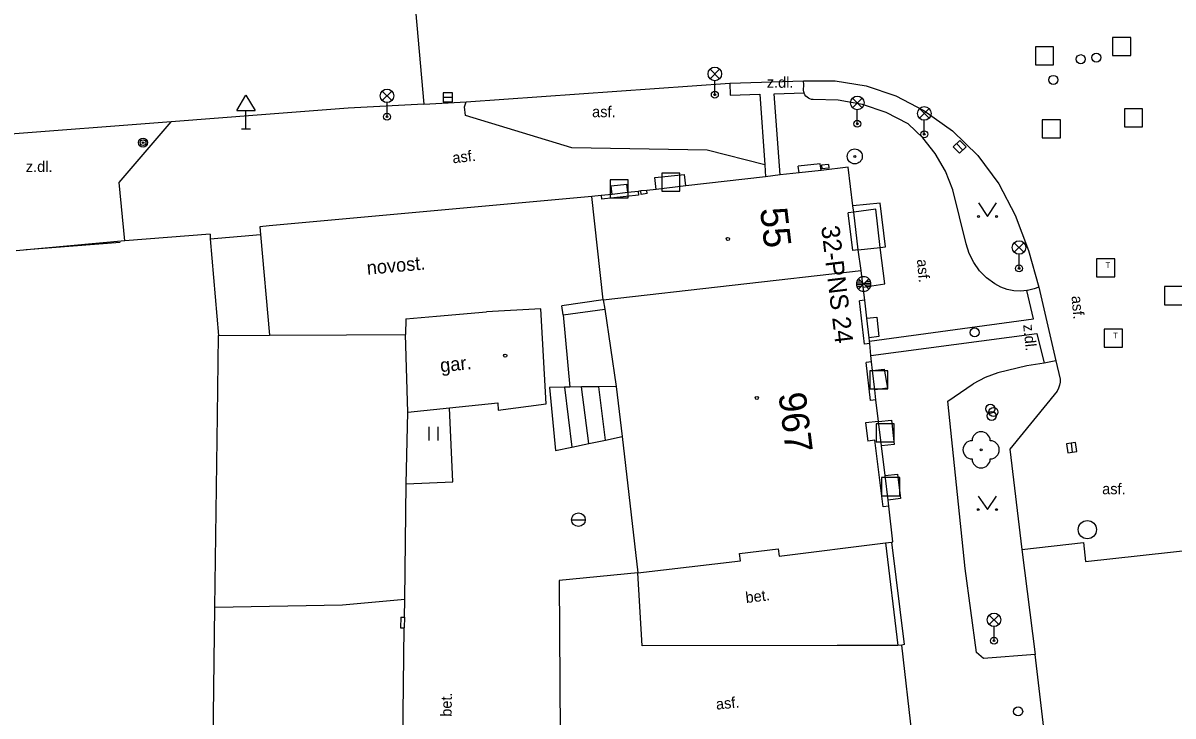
# Model space of a CAD drawing. Extents: x -642282 to -641982, y -1041678 to -1041427.
# Drawn here: x -642233.5 to -642170.1, y -1041615 to -1041576.8 of the extents above; entities that cross this region are included whole.
import ezdxf

# ---------------------------------------------------------------- set-up
doc = ezdxf.new("R2010")
doc.units = 0
for name, color, linetype in [('Budovy', 7, 'Continuous'), ('Budovy vstupy', 7, 'Continuous'), ('Nivel_zn_-popis', 7, 'Continuous'), ('Nivel_značky', 7, 'Continuous'), ('Ploty', 7, 'Continuous'), ('Pol_bod_pole', 7, 'Continuous'), ('Popis objektů', 7, 'Continuous'), ('Popis povrchů', 7, 'Continuous'), ('Popis ČP_ ČE', 7, 'Continuous'), ('Pris-HUP', 7, 'Continuous'), ('Rozhraní ploch 1', 7, 'Continuous'), ('Rozhraní ploch 2', 7, 'Continuous'), ('Sloupy_označník', 7, 'Continuous'), ('Vstup na pozemky', 7, 'Continuous'), ('Zeleň - stromy', 7, 'Continuous'), ('Znaky doprava', 7, 'Continuous'), ('Znaky kanalizace', 7, 'Continuous'), ('Znaky voda', 7, 'Continuous'), ('Značky doprava', 7, 'Continuous'), ('Značky KM', 7, 'Continuous'), ('Značky předmětů', 7, 'Continuous'), ('Značky těžba', 7, 'Continuous'), ('Šachta teplo', 7, 'Continuous'), ('Šachty ner_', 7, 'Continuous')]:
    doc.layers.add(name, color=color, linetype=linetype)

msp = doc.modelspace()

# ---------------------------------------------------------------- linework, layer by layer
at = {"layer": 'Budovy'}
for p, q in [((-642188.02, -1041584.72), (-642189.518, -1041584.892)), ((-642187.762, -1041586.844), (-642188.02, -1041584.72)), ((-642192.575, -1041585.236), (-642196.959, -1041585.747)), ((-642191.765, -1041585.143), (-642192.575, -1041585.236)), ((-642190.726, -1041585.031), (-642191.765, -1041585.143)), ((-642189.518, -1041584.892), (-642190.726, -1041585.031)), ((-642198.594, -1041585.934), (-642199.116, -1041585.994)), ((-642196.959, -1041585.747), (-642198.594, -1041585.934)), ((-642202.14, -1041586.33), (-642219.914, -1041587.952)), ((-642201.64, -1041586.28), (-642202.14, -1041586.33)), ((-642201.515, -1041592.02), (-642202.14, -1041586.33)), ((-642201.027, -1041586.211), (-642201.64, -1041586.28)), ((-642201.64, -1041586.28), (-642201.618, -1041586.479)), ((-642199.578, -1041586.249), (-642201.618, -1041586.479)), ((-642200.161, -1041586.113), (-642201.027, -1041586.211)), ((-642199.6, -1041586.05), (-642200.161, -1041586.113)), ((-642199.45, -1041586.02), (-642199.6, -1041586.05)), ((-642199.6, -1041586.05), (-642199.578, -1041586.249)), ((-642199.116, -1041585.994), (-642199.45, -1041586.02)), ((-642187.72, -1041587.19), (-642188.018, -1041587.226)), ((-642187.768, -1041589.306), (-642188.018, -1041587.226)), ((-642187.72, -1041587.19), (-642187.762, -1041586.844)), ((-642187.47, -1041589.27), (-642187.72, -1041587.19)), ((-642223.171, -1041588.406), (-642227.872, -1041588.766)), ((-642219.914, -1041587.952), (-642220.44, -1041588)), ((-642220.44, -1041588), (-642220.401, -1041588.424)), ((-642220.401, -1041588.424), (-642219.895, -1041593.974)), ((-642227.872, -1041588.766), (-642233.854, -1041589.321)), ((-642223.167, -1041588.668), (-642222.72, -1041593.99)), ((-642187.47, -1041589.27), (-642187.768, -1041589.306)), ((-642187.308, -1041590.4), (-642187.47, -1041589.27)), ((-642201.515, -1041592.02), (-642187.308, -1041590.4)), ((-642187.197, -1041591.322), (-642187.308, -1041590.4)), ((-642187.11, -1041592.04), (-642187.197, -1041591.322)), ((-642201.515, -1041592.02), (-642201.438, -1041592.538)), ((-642187.11, -1041592.04), (-642187.408, -1041592.075)), ((-642187.128, -1041594.465), (-642187.408, -1041592.075)), ((-642186.993, -1041593.035), (-642187.11, -1041592.04)), ((-642212.4, -1041593.07), (-642210.71, -1041592.93)), ((-642210.71, -1041592.93), (-642207.953, -1041592.68)), ((-642204.958, -1041592.512), (-642207.953, -1041592.68)), ((-642204.665, -1041597.747), (-642204.958, -1041592.512)), ((-642201.438, -1041592.538), (-642200.805, -1041596.8)), ((-642212.4, -1041593.07), (-642212.41, -1041593.93)), ((-642186.868, -1041594.109), (-642186.993, -1041593.035)), ((-642222.77, -1041598.39), (-642222.72, -1041593.99)), ((-642222.72, -1041593.99), (-642219.895, -1041593.974)), ((-642219.895, -1041593.974), (-642215.66, -1041593.95)), ((-642215.66, -1041593.95), (-642212.41, -1041593.93)), ((-642212.275, -1041598.207), (-642212.41, -1041593.93)), ((-642186.845, -1041594.303), (-642186.868, -1041594.109)), ((-642186.83, -1041594.43), (-642187.128, -1041594.465)), ((-642186.83, -1041594.43), (-642186.845, -1041594.303)), ((-642186.771, -1041595.088), (-642186.83, -1041594.43)), ((-642186.74, -1041595.44), (-642187.038, -1041595.474)), ((-642186.796, -1041597.571), (-642187.038, -1041595.474)), ((-642186.74, -1041595.44), (-642186.771, -1041595.088)), ((-642186.685, -1041595.915), (-642186.74, -1041595.44)), ((-642186.563, -1041596.975), (-642186.685, -1041595.915)), ((-642200.805, -1041596.8), (-642200.483, -1041599.557)), ((-642186.498, -1041597.537), (-642186.563, -1041596.975)), ((-642212.275, -1041598.207), (-642209.98, -1041597.972)), ((-642209.98, -1041597.972), (-642207.322, -1041597.699)), ((-642207.322, -1041597.699), (-642207.313, -1041598.099)), ((-642207.313, -1041598.099), (-642204.665, -1041597.747)), ((-642186.498, -1041597.537), (-642186.796, -1041597.571)), ((-642186.36, -1041598.73), (-642186.498, -1041597.537)), ((-642222.91, -1041608.98), (-642222.77, -1041598.39)), ((-642212.379, -1041602.169), (-642212.275, -1041598.207)), ((-642186.36, -1041598.73), (-642187.063, -1041598.811)), ((-642187.063, -1041598.811), (-642186.947, -1041599.809)), ((-642186.193, -1041600.076), (-642186.36, -1041598.73)), ((-642200.483, -1041599.557), (-642199.604, -1041607.074)), ((-642186.55, -1041599.76), (-642186.947, -1041599.809)), ((-642186.094, -1041603.433), (-642186.55, -1041599.76)), ((-642185.991, -1041601.704), (-642186.193, -1041600.076)), ((-642185.822, -1041603.058), (-642185.991, -1041601.704)), ((-642212.452, -1041608.543), (-642212.379, -1041602.169)), ((-642185.78, -1041603.4), (-642185.822, -1041603.058)), ((-642185.78, -1041603.4), (-642186.094, -1041603.433)), ((-642185.562, -1041605.368), (-642185.78, -1041603.4)), ((-642191.831, -1041606.151), (-642185.97, -1041605.416)), ((-642185.97, -1041605.416), (-642185.632, -1041605.386)), ((-642185.632, -1041605.386), (-642185.562, -1041605.368)), ((-642194.006, -1041606.007), (-642191.878, -1041605.754)), ((-642193.959, -1041606.404), (-642194.006, -1041606.007)), ((-642191.878, -1041605.754), (-642191.831, -1041606.151)), ((-642199.604, -1041607.074), (-642193.959, -1041606.404)), ((-642212.452, -1041608.543), (-642215.88, -1041608.86)), ((-642212.47, -1041609.52), (-642212.452, -1041608.543)), ((-642223.08, -1041622.83), (-642222.91, -1041608.98)), ((-642215.88, -1041608.86), (-642222.91, -1041608.98)), ((-642212.47, -1041609.52), (-642212.48, -1041610.1)), ((-642212.692, -1041625.83), (-642212.48, -1041610.1))]:
    msp.add_line(p, q, dxfattribs=at)
msp.add_lwpolyline([(-642223.171, -1041588.406), (-642223.167, -1041588.668)], dxfattribs=at)
at = {"layer": 'Budovy vstupy'}
msp.add_line((-642228.136, -1041588.865), (-642233.302, -1041589.262), dxfattribs=at)
at = {"layer": 'Nivel_značky'}
for p, q in [((-642187.328, -1041590.999), (-642187.519, -1041590.999)), ((-642187.17, -1041591.15), (-642187.455, -1041590.865)), ((-642186.885, -1041590.865), (-642187.17, -1041591.15)), ((-642186.822, -1041591.015), (-642187.025, -1041591.015)), ((-642187.244, -1041591.11), (-642187.57, -1041591.11)), ((-642187.244, -1041591.205), (-642187.542, -1041591.205)), ((-642187.345, -1041591.31), (-642187.531, -1041591.31)), ((-642187.455, -1041591.435), (-642187.17, -1041591.15)), ((-642187.17, -1041591.15), (-642186.885, -1041591.435)), ((-642186.794, -1041591.115), (-642187.115, -1041591.115)), ((-642186.8, -1041591.215), (-642187.081, -1041591.215)), ((-642186.828, -1041591.305), (-642187.008, -1041591.305))]:
    msp.add_line(p, q, dxfattribs=at)
for start, end in [(135, 225), (45, 135), (315, 45), (225, 315)]:
    msp.add_arc((-642187.17, -1041591.15), 0.403, start, end, dxfattribs=at)
at = {"layer": 'Ploty'}
for p, q in [((-642223.167, -1041588.668), (-642220.401, -1041588.424)), ((-642201.515, -1041592.02), (-642203.804, -1041592.363)), ((-642203.73, -1041592.857), (-642203.804, -1041592.363)), ((-642203.73, -1041592.857), (-642201.438, -1041592.538)), ((-642185.97, -1041605.416), (-642185.295, -1041611.069)), ((-642185.632, -1041605.386), (-642184.948, -1041611.027)), ((-642185.061, -1041611.058), (-642185.295, -1041611.069)), ((-642184.948, -1041611.027), (-642185.061, -1041611.058))]:
    msp.add_line(p, q, dxfattribs=at)
at = {"layer": 'Pol_bod_pole'}
for radius in [0.412, 0.05]:
    msp.add_circle((-642187.66, -1041584.12), radius, dxfattribs=at)
at = {"layer": 'Pris-HUP'}
for p, q in [((-642189.56, -1041584.53), (-642190.77, -1041584.65)), ((-642190.726, -1041585.031), (-642190.77, -1041584.65)), ((-642189.518, -1041584.892), (-642189.56, -1041584.53)), ((-642189.11, -1041584.56), (-642189.49, -1041584.6)), ((-642189.49, -1041584.6), (-642189.469, -1041584.799)), ((-642189.11, -1041584.56), (-642189.089, -1041584.759)), ((-642189.089, -1041584.759), (-642189.469, -1041584.799)), ((-642199.42, -1041586.218), (-642199.45, -1041586.02)), ((-642199.09, -1041586.168), (-642199.42, -1041586.218)), ((-642199.09, -1041586.168), (-642199.116, -1041585.994)), ((-642212.67, -1041609.517), (-642212.68, -1041610.097)), ((-642212.67, -1041609.517), (-642212.47, -1041609.52)), ((-642212.68, -1041610.097), (-642212.48, -1041610.1))]:
    msp.add_line(p, q, dxfattribs=at)
at = {"layer": 'Rozhraní ploch 1'}
for p, q in [((-642211.41, -1041581.24), (-642215.565, -1041581.462)), ((-642225.323, -1041582.22), (-642236.723, -1041583.094)), ((-642203.73, -1041592.857), (-642203.361, -1041596.833)), ((-642186.993, -1041593.035), (-642186.439, -1041592.97)), ((-642186.439, -1041592.97), (-642186.334, -1041594.047)), ((-642186.334, -1041594.047), (-642186.868, -1041594.109)), ((-642186.685, -1041595.915), (-642186.036, -1041595.84)), ((-642186.036, -1041595.84), (-642185.861, -1041596.893)), ((-642182.53, -1041597.61), (-642181.14, -1041596.66)), ((-642203.66, -1041596.837), (-642204.469, -1041596.847)), ((-642204.469, -1041596.847), (-642204.148, -1041600.333)), ((-642203.361, -1041596.833), (-642203.66, -1041596.837)), ((-642203.66, -1041596.837), (-642203.243, -1041600.141)), ((-642202.712, -1041596.824), (-642203.361, -1041596.833)), ((-642201.768, -1041596.812), (-642202.712, -1041596.824)), ((-642202.319, -1041599.946), (-642202.712, -1041596.824)), ((-642200.805, -1041596.8), (-642201.768, -1041596.812)), ((-642201.397, -1041599.751), (-642201.768, -1041596.812)), ((-642185.861, -1041596.893), (-642186.563, -1041596.975)), ((-642209.797, -1041602.061), (-642209.98, -1041597.972)), ((-642181.57, -1041606.84), (-642182.53, -1041597.61)), ((-642186.36, -1041598.73), (-642185.629, -1041598.655)), ((-642185.629, -1041598.655), (-642185.485, -1041599.993)), ((-642202.319, -1041599.946), (-642201.397, -1041599.751)), ((-642201.397, -1041599.751), (-642200.483, -1041599.557)), ((-642204.148, -1041600.333), (-642203.243, -1041600.141)), ((-642203.243, -1041600.141), (-642202.319, -1041599.946)), ((-642185.485, -1041599.993), (-642186.193, -1041600.076)), ((-642185.991, -1041601.704), (-642185.306, -1041601.624)), ((-642185.306, -1041601.624), (-642185.142, -1041602.979)), ((-642212.379, -1041602.169), (-642209.797, -1041602.061)), ((-642185.142, -1041602.979), (-642185.822, -1041603.058)), ((-642178.45, -1041605.79), (-642177.73, -1041611.57)), ((-642180.96, -1041611.46), (-642181.57, -1041606.84)), ((-642199.604, -1041607.074), (-642203.947, -1041607.486)), ((-642203.947, -1041607.486), (-642203.888, -1041615.923)), ((-642199.367, -1041611.101), (-642199.604, -1041607.074)), ((-642188.631, -1041611.067), (-642199.367, -1041611.101)), ((-642185.295, -1041611.069), (-642188.631, -1041611.067)), ((-642180.56, -1041611.8), (-642180.96, -1041611.46)), ((-642177.73, -1041611.57), (-642180.56, -1041611.8)), ((-642177.25, -1041615.63), (-642177.73, -1041611.57))]:
    msp.add_line(p, q, dxfattribs=at)
for points in [[(-642209.07, -1041581.11), (-642194.55, -1041580.09)], [(-642194.55, -1041580.09), (-642190.48, -1041579.95), (-642188.748, -1041579.955), (-642187.039, -1041580.234), (-642185.396, -1041580.78)], [(-642190.47, -1041580.18), (-642190.48, -1041579.95)], [(-642182.669, -1041584.927), (-642183.223, -1041583.964), (-642183.912, -1041583.092), (-642184.72, -1041582.33), (-642185.938, -1041581.704), (-642187.234, -1041581.265), (-642188.582, -1041581.022), (-642189.95, -1041580.98), (-642190.041, -1041580.973), (-642190.13, -1041580.95), (-642190.213, -1041580.912), (-642190.288, -1041580.86), (-642190.35, -1041580.8), (-642190.407, -1041580.722), (-642190.446, -1041580.639), (-642190.455, -1041580.613), (-642190.471, -1041580.551), (-642190.48, -1041580.46), (-642190.47, -1041580.18)], [(-642185.396, -1041580.78), (-642183.86, -1041581.58), (-642182.276, -1041582.711), (-642180.887, -1041584.075), (-642179.725, -1041585.637), (-642178.82, -1041587.36)], [(-642215.565, -1041581.462), (-642220.347, -1041581.834), (-642225.323, -1041582.22)], [(-642211.41, -1041581.24), (-642209.07, -1041581.11)], [(-642177.52, -1041591.32), (-642177.77, -1041591.41), (-642178.136, -1041591.504), (-642178.173, -1041591.508), (-642178.512, -1041591.543), (-642178.889, -1041591.526), (-642179.26, -1041591.454), (-642179.616, -1041591.328), (-642179.95, -1041591.15), (-642180.396, -1041590.817), (-642180.786, -1041590.42), (-642181.11, -1041589.967), (-642181.36, -1041589.47), (-642181.53, -1041588.94), (-642182.26, -1041585.96), (-642182.669, -1041584.927)], [(-642178.82, -1041587.36), (-642178.082, -1041589.311)], [(-642178.082, -1041589.311), (-642177.52, -1041591.32), (-642176.583, -1041595.381), (-642176.35, -1041596.39), (-642176.354, -1041596.562), (-642176.38, -1041596.72), (-642176.435, -1041596.895), (-642176.51, -1041597.05)], [(-642176.583, -1041595.381), (-642177.22, -1041595.51), (-642178.187, -1041595.666), (-642179.77, -1041596.05)], [(-642179.77, -1041596.05), (-642180.477, -1041596.305), (-642181.14, -1041596.66)], [(-642176.51, -1041597.05), (-642179.12, -1041600.26)], [(-642179.12, -1041600.26), (-642178.45, -1041605.79)]]:
    msp.add_lwpolyline(points, dxfattribs=at)
at = {"layer": 'Rozhraní ploch 2'}
for p, q in [((-642203.24, -1041583.64), (-642209.11, -1041581.87)), ((-642195.79, -1041583.78), (-642203.24, -1041583.64)), ((-642192.62, -1041584.586), (-642195.79, -1041583.78)), ((-642198.67, -1041585.284), (-642197.032, -1041585.117)), ((-642198.594, -1041585.934), (-642198.67, -1041585.284)), ((-642196.959, -1041585.747), (-642197.032, -1041585.117)), ((-642201.082, -1041585.732), (-642200.215, -1041585.649)), ((-642201.027, -1041586.211), (-642201.082, -1041585.732)), ((-642200.161, -1041586.113), (-642200.215, -1041585.649)), ((-642186.27, -1041586.69), (-642187.762, -1041586.844)), ((-642186.5, -1041587.02), (-642187.72, -1041587.19)), ((-642186.27, -1041589.14), (-642186.5, -1041587.02)), ((-642185.96, -1041589.11), (-642186.27, -1041586.69)), ((-642187.47, -1041589.27), (-642186.27, -1041589.14)), ((-642186.27, -1041589.14), (-642185.96, -1041589.11)), ((-642186.01, -1041591.14), (-642186.27, -1041589.14)), ((-642187.197, -1041591.322), (-642186.01, -1041591.14)), ((-642177.82, -1041593.07), (-642178.173, -1041591.508)), ((-642186.845, -1041594.303), (-642177.82, -1041593.07)), ((-642186.771, -1041595.088), (-642177.63, -1041593.87)), ((-642177.63, -1041593.87), (-642177.22, -1041595.51))]:
    msp.add_line(p, q, dxfattribs=at)
for points in [[(-642212.04, -1041573.97), (-642211.41, -1041581.24)], [(-642194.55, -1041580.09), (-642194.516, -1041580.736), (-642192.89, -1041580.68), (-642192.62, -1041584.586), (-642192.575, -1041585.236)], [(-642191.765, -1041585.143), (-642192.1, -1041580.67), (-642190.455, -1041580.613)], [(-642209.11, -1041581.87), (-642209.16, -1041581.38), (-642209.07, -1041581.11)], [(-642227.872, -1041588.766), (-642228.188, -1041585.548), (-642225.323, -1041582.22)], [(-642178.45, -1041605.79), (-642175.06, -1041605.39), (-642174.95, -1041606.44)], [(-642174.95, -1041606.44), (-642168.77, -1041605.77)]]:
    msp.add_lwpolyline(points, dxfattribs=at)
at = {"layer": 'Sloupy_označník'}
for radius in [0.25, 0.158, 0.05]:
    msp.add_circle((-642226.87, -1041583.36), radius, dxfattribs=at)
at = {"layer": 'Vstup na pozemky'}
msp.add_line((-642184.49, -1041616.05), (-642185.061, -1041611.058), dxfattribs=at)
at = {"layer": 'Zeleň - stromy'}
msp.add_circle((-642180.7, -1041600.29), 0.05, dxfattribs=at)
for centre, start, end in [((-642180.7, -1041599.79), 0, 180), ((-642181.2, -1041600.29), 90, 270), ((-642180.2, -1041600.29), 270, 90), ((-642180.7, -1041600.79), 180, 0)]:
    msp.add_arc(centre, 0.5, start, end, dxfattribs=at)
at = {"layer": 'Znaky doprava'}
for p, q in [((-642195.635, -1041579.305), (-642195.105, -1041579.835)), ((-642195.635, -1041579.835), (-642195.105, -1041579.305)), ((-642195.37, -1041580.72), (-642195.37, -1041579.945)), ((-642213.695, -1041580.515), (-642213.165, -1041581.045)), ((-642213.695, -1041581.045), (-642213.165, -1041580.515)), ((-642187.785, -1041580.905), (-642187.255, -1041581.435)), ((-642187.785, -1041581.435), (-642187.255, -1041580.905)), ((-642213.43, -1041581.93), (-642213.43, -1041581.155)), ((-642187.52, -1041582.32), (-642187.52, -1041581.545)), ((-642184.095, -1041581.485), (-642183.565, -1041582.015)), ((-642184.095, -1041582.015), (-642183.565, -1041581.485)), ((-642183.83, -1041582.9), (-642183.83, -1041582.125)), ((-642178.875, -1041588.875), (-642178.345, -1041589.405)), ((-642178.875, -1041589.405), (-642178.345, -1041588.875)), ((-642178.61, -1041590.29), (-642178.61, -1041589.515)), ((-642180.255, -1041609.395), (-642179.725, -1041609.925)), ((-642180.255, -1041609.925), (-642179.725, -1041609.395)), ((-642179.99, -1041610.81), (-642179.99, -1041610.035))]:
    msp.add_line(p, q, dxfattribs=at)
for centre, radius in [((-642195.37, -1041579.57), 0.375), ((-642213.43, -1041580.78), 0.375), ((-642195.37, -1041580.72), 0.19), ((-642195.37, -1041580.72), 0.05), ((-642187.52, -1041581.17), 0.375), ((-642183.83, -1041581.75), 0.375), ((-642213.43, -1041581.93), 0.19), ((-642213.43, -1041581.93), 0.05), ((-642187.52, -1041582.32), 0.19), ((-642187.52, -1041582.32), 0.05), ((-642183.83, -1041582.9), 0.19), ((-642183.83, -1041582.9), 0.05), ((-642178.61, -1041589.14), 0.375), ((-642178.61, -1041590.29), 0.19), ((-642178.61, -1041590.29), 0.05), ((-642179.99, -1041609.66), 0.375), ((-642179.99, -1041610.81), 0.19), ((-642179.99, -1041610.81), 0.05)]:
    msp.add_circle(centre, radius, dxfattribs=at)
at = {"layer": 'Znaky kanalizace'}
for p, q in [((-642210.33, -1041580.86), (-642209.83, -1041580.86)), ((-642182.056, -1041583.412), (-642181.704, -1041583.768)), ((-642175.741, -1041599.922), (-642175.679, -1041600.418))]:
    msp.add_line(p, q, dxfattribs=at)
for points in [[(-642210.33, -1041581.11), (-642209.83, -1041581.11), (-642209.83, -1041580.61), (-642210.33, -1041580.61)], [(-642182.234, -1041583.588), (-642181.882, -1041583.944), (-642181.526, -1041583.592), (-642181.878, -1041583.236)], [(-642175.989, -1041599.953), (-642175.927, -1041600.449), (-642175.431, -1041600.387), (-642175.493, -1041599.891)]]:
    msp.add_lwpolyline(points, close=True, dxfattribs=at)
msp.add_circle((-642174.85, -1041604.69), 0.5, dxfattribs=at)
at = {"layer": 'Znaky voda'}
for centre in [(-642175.21, -1041578.76), (-642174.35, -1041578.67), (-642176.72, -1041579.9), (-642181.06, -1041593.82), (-642180.19, -1041598.03), (-642180.02, -1041598.21), (-642180.12, -1041598.42), (-642178.66, -1041614.71)]:
    msp.add_circle(centre, 0.25, dxfattribs=at)
at = {"layer": 'Značky doprava'}
for p, q in [((-642221.7, -1041581.59), (-642221.2, -1041580.74)), ((-642221.2, -1041580.74), (-642220.7, -1041581.59)), ((-642221.7, -1041581.59), (-642220.7, -1041581.59)), ((-642221.2, -1041582.59), (-642221.2, -1041581.59)), ((-642221.45, -1041582.59), (-642220.95, -1041582.59))]:
    msp.add_line(p, q, dxfattribs=at)
at = {"layer": 'Značky KM'}
for p, q in [((-642180.847, -1041586.682), (-642180.347, -1041587.432)), ((-642180.347, -1041587.432), (-642179.847, -1041586.682)), ((-642211.103, -1041599.772), (-642211.103, -1041599.022)), ((-642210.603, -1041599.772), (-642210.603, -1041599.022)), ((-642180.856, -1041602.835), (-642180.356, -1041603.585)), ((-642180.356, -1041603.585), (-642179.856, -1041602.835))]:
    msp.add_line(p, q, dxfattribs=at)
for centre in [(-642180.847, -1041587.432), (-642179.847, -1041587.432), (-642180.856, -1041603.585), (-642179.856, -1041603.585)]:
    msp.add_circle(centre, 0.05, dxfattribs=at)
at = {"layer": 'Značky předmětů'}
for centre in [(-642194.651, -1041588.667), (-642206.917, -1041595.1), (-642193.054, -1041597.432)]:
    msp.add_circle(centre, 0.0875, dxfattribs=at)
at = {"layer": 'Značky těžba'}
msp.add_line((-642203.259, -1041604.142), (-642202.509, -1041604.142), dxfattribs=at)
msp.add_circle((-642202.884, -1041604.142), 0.375, dxfattribs=at)
at = {"layer": 'Šachta teplo'}
for points in [[(-642174.34, -1041590.76), (-642173.34, -1041590.76), (-642173.34, -1041589.76), (-642174.34, -1041589.76)], [(-642170.59, -1041592.29), (-642169.59, -1041592.29), (-642169.59, -1041591.29), (-642170.59, -1041591.29)], [(-642173.92, -1041594.64), (-642172.92, -1041594.64), (-642172.92, -1041593.64), (-642173.92, -1041593.64)]]:
    msp.add_lwpolyline(points, close=True, dxfattribs=at)
at = {"layer": 'Šachty ner_'}
for points in [[(-642173.46, -1041578.56), (-642172.46, -1041578.56), (-642172.46, -1041577.56), (-642173.46, -1041577.56)], [(-642177.71, -1041579.07), (-642176.71, -1041579.07), (-642176.71, -1041578.07), (-642177.71, -1041578.07)], [(-642172.81, -1041582.49), (-642171.81, -1041582.49), (-642171.81, -1041581.49), (-642172.81, -1041581.49)], [(-642177.33, -1041583.1), (-642176.33, -1041583.1), (-642176.33, -1041582.1), (-642177.33, -1041582.1)], [(-642198.29, -1041586.04), (-642197.29, -1041586.04), (-642197.29, -1041585.04), (-642198.29, -1041585.04)], [(-642201.14, -1041586.41), (-642200.14, -1041586.41), (-642200.14, -1041585.41), (-642201.14, -1041585.41)], [(-642186.83, -1041596.93), (-642185.83, -1041596.93), (-642185.83, -1041595.93), (-642186.83, -1041595.93)], [(-642186.49, -1041599.85), (-642185.49, -1041599.85), (-642185.49, -1041598.85), (-642186.49, -1041598.85)], [(-642186.18, -1041602.82), (-642185.18, -1041602.82), (-642185.18, -1041601.82), (-642186.18, -1041601.82)]]:
    msp.add_lwpolyline(points, close=True, dxfattribs=at)

# ---------------------------------------------------------------- texts
at = {"layer": 'Nivel_zn_-popis'}
msp.add_text('32-PNS 24', height=1, rotation=276.86482, dxfattribs=at).set_placement((-642189.513, -1041587.983))
at = {"layer": 'Popis objektů'}
for s, rotation, p in [('novost.', 5.21419, (-642214.513, -1041590.641)), ('gar.', 5.86422, (-642210.466, -1041596.013))]:
    msp.add_text(s, height=0.75, rotation=rotation, dxfattribs=at).set_placement(p)
at = {"layer": 'Popis povrchů'}
for s, p in [('z.dl.', (-642192.508, -1041580.338)), ('asf.', (-642202.132, -1041581.956)), ('z.dl.', (-642233.328, -1041584.977)), ('asf.', (-642174.032, -1041602.74))]:
    msp.add_text(s, height=0.6, dxfattribs=at).set_placement(p)
for s, rotation, p in [('asf.', 6.54773, (-642209.798, -1041584.502)), ('asf.', 275.08638, (-642184.237, -1041589.804)), ('asf.', 275.08638, (-642175.722, -1041591.825)), ('z.dl.', 275.96056, (-642178.385, -1041593.401)), ('bet.', 6.76872, (-642193.644, -1041608.736)), ('bet.', 89.22785, (-642209.873, -1041615.006)), ('asf.', 5.70089, (-642195.282, -1041614.613))]:
    msp.add_text(s, height=0.6, rotation=rotation, dxfattribs=at).set_placement(p)
at = {"layer": 'Popis ČP_ ČE'}
for s, rotation, p in [('55', 276.637, (-642192.885, -1041587.009)), ('967', 277.152, (-642191.868, -1041597.205))]:
    msp.add_text(s, height=1.5, rotation=rotation, dxfattribs=at).set_placement(p)
at = {"layer": 'Šachta teplo'}
for p in [(-642173.84, -1041590.26), (-642173.42, -1041594.14)]:
    msp.add_text('T', height=0.3, dxfattribs=at).set_placement(p)

doc.saveas('drawing.dxf')
